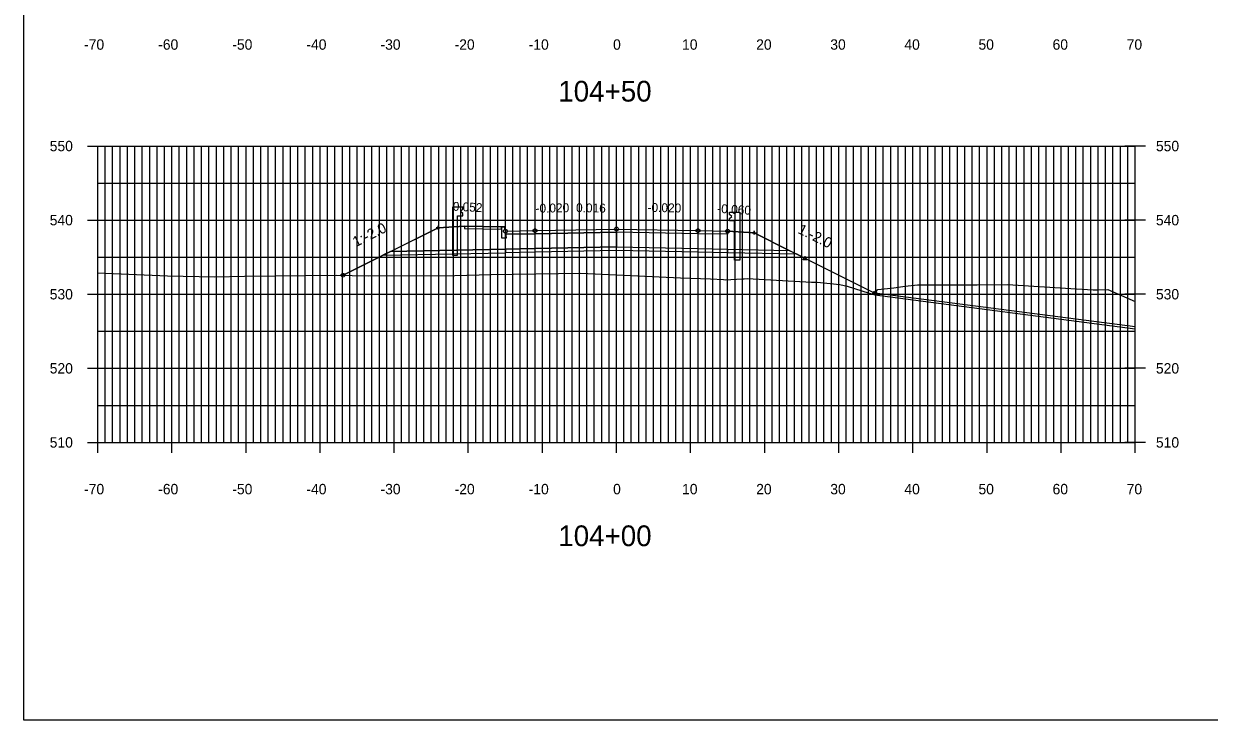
# Model space of a CAD drawing. Extents: x 1509063 to 1512863, y 401160 to 402918.
# Drawn here: x 1511822.7 to 1511982.7, y 402252.1 to 402346.1 of the extents above; entities that cross this region are included whole.
import ezdxf

# ---------------------------------------------------------------- set-up
doc = ezdxf.new("R2010")
doc.units = 0
for name, color, linetype in [('DD_P', 7, 'Continuous'), ('DDG_P', 7, 'Continuous'), ('LFILL_P', 7, 'Continuous'), ('NBL1', 7, 'Continuous'), ('PET_P', 7, 'Continuous'), ('PRC', 7, 'Continuous'), ('PSP_P', 7, 'Continuous'), ('RBS_P', 7, 'Continuous'), ('RCC_P', 7, 'Continuous'), ('RGR_P', 7, 'Continuous'), ('XAX_P', 7, 'Continuous'), ('XAXTIC_P', 7, 'Continuous'), ('XAXTXT_P_T', 7, 'Continuous'), ('XGL_P', 7, 'Continuous'), ('XSL1_P', 7, 'Continuous'), ('XSL1_P_T', 7, 'Continuous'), ('XSL2_P', 7, 'Continuous'), ('XSL3_P', 7, 'Continuous'), ('XSLOG', 7, 'Continuous')]:
    doc.layers.add(name, color=color, linetype=linetype)

msp = doc.modelspace()

# ---------------------------------------------------------------- linework, layer by layer
at = {"layer": 'DD_P'}
msp.add_lwpolyline([(1511928.15, 402314.7), (1511928.4, 402314.2), (1511927.9, 402314.2)], close=True, dxfattribs=at)
at = {"layer": 'DDG_P'}
msp.add_lwpolyline([(1511972.73, 402304.91), (1511972.73, 402305.16), (1511937.59, 402309.73), (1511937.59, 402309.48)], close=True, dxfattribs=at)
at = {"layer": 'LFILL_P'}
for points in [[(1511882.23, 402318.77), (1511878.65, 402318.56), (1511865.82, 402312.15)], [(1511917.73, 402318.08), (1511921.31, 402317.87), (1511928.15, 402314.45), (1511937.59, 402309.73)]]:
    msp.add_lwpolyline(points, dxfattribs=at)
for centre in [(1511865.82, 402312.15), (1511937.59, 402309.73)]:
    msp.add_circle(centre, 0.25, dxfattribs=at)
at = {"layer": 'NBL1'}
msp.add_lwpolyline([(1512142.73, 402252.08), (1511822.73, 402252.08), (1511822.73, 402462.08), (1512142.73, 402462.08)], close=True, dxfattribs=at)
at = {"layer": 'PET_P'}
for centre in [(1511891.73, 402318.16), (1511913.73, 402318.16)]:
    msp.add_circle(centre, 0.25, dxfattribs=at)
at = {"layer": 'PRC'}
msp.add_circle((1511902.73, 402318.38), 0.25, dxfattribs=at)
at = {"layer": 'PSP_P'}
for centre in [(1511887.73, 402318.08), (1511917.73, 402318.08)]:
    msp.add_circle(centre, 0.25, dxfattribs=at)
at = {"layer": 'RBS_P'}
for points in [[(1511887.8, 402317.67), (1511891.73, 402317.75), (1511902.73, 402317.97), (1511902.73, 402315.97), (1511891.73, 402315.75), (1511887.8, 402315.67), (1511872.24, 402315.36), (1511878.65, 402318.56), (1511882.23, 402318.77), (1511882.23, 402318.44), (1511887.23, 402318.34), (1511887.23, 402317.17), (1511887.88, 402317.17)], [(1511902.73, 402317.97), (1511902.73, 402315.97), (1511913.73, 402315.75), (1511917.73, 402315.67), (1511926.05, 402315.5), (1511921.31, 402317.87), (1511917.73, 402318.08), (1511917.73, 402317.67), (1511913.73, 402317.75)]]:
    msp.add_lwpolyline(points, close=True, dxfattribs=at)
for points in [[(1511878.65, 402318.56), (1511878.65, 402318.81), (1511878.65, 402318.56), (1511878.4, 402318.56), (1511878.65, 402318.56), (1511878.65, 402318.31), (1511878.65, 402318.56), (1511878.9, 402318.56)], [(1511921.31, 402317.87), (1511921.31, 402318.12), (1511921.31, 402317.87), (1511921.06, 402317.87), (1511921.31, 402317.87), (1511921.31, 402317.62), (1511921.31, 402317.87), (1511921.56, 402317.87)]]:
    msp.add_lwpolyline(points, dxfattribs=at)
at = {"layer": 'RCC_P'}
msp.add_lwpolyline([(1511887.73, 402318.08), (1511887.63, 402318.67), (1511887.23, 402318.67), (1511887.23, 402317.17), (1511887.88, 402317.17)], close=True, dxfattribs=at)
at = {"layer": 'RGR_P'}
for points in [[(1511881.29, 402320.18), (1511881.98, 402320.18), (1511881.98, 402320.48), (1511881.68, 402320.76), (1511881.98, 402321.05), (1511881.98, 402321.35), (1511880.6, 402321.35), (1511880.6, 402314.85), (1511881.29, 402314.85)], [(1511918.66, 402319.48), (1511917.98, 402319.48), (1511917.98, 402319.78), (1511918.28, 402320.07), (1511917.98, 402320.36), (1511917.98, 402320.66), (1511919.36, 402320.66), (1511919.36, 402314.16), (1511918.66, 402314.16)]]:
    msp.add_lwpolyline(points, close=True, dxfattribs=at)
at = {"layer": 'XAX_P'}
for p, q in [((1511832.73, 402289.58), (1511832.73, 402329.58)), ((1511902.73, 402289.58), (1511902.73, 402329.58)), ((1511972.73, 402289.58), (1511972.73, 402329.58)), ((1511832.73, 402289.58), (1511972.73, 402289.58))]:
    msp.add_line(p, q, dxfattribs=at)
at = {"layer": 'XAXTIC_P'}
for p, q in [((1511831.33, 402329.58), (1511834.13, 402329.58)), ((1511901.33, 402329.58), (1511904.13, 402329.58)), ((1511974.13, 402329.58), (1511971.33, 402329.58)), ((1511831.33, 402319.58), (1511834.13, 402319.58)), ((1511901.33, 402319.58), (1511904.13, 402319.58)), ((1511974.13, 402319.58), (1511971.33, 402319.58)), ((1511831.33, 402309.58), (1511834.13, 402309.58)), ((1511901.33, 402309.58), (1511904.13, 402309.58)), ((1511974.13, 402309.58), (1511971.33, 402309.58)), ((1511831.33, 402299.58), (1511834.13, 402299.58)), ((1511901.33, 402299.58), (1511904.13, 402299.58)), ((1511974.13, 402299.58), (1511971.33, 402299.58)), ((1511832.73, 402288.18), (1511832.73, 402290.98)), ((1511842.73, 402288.18), (1511842.73, 402290.98)), ((1511852.73, 402288.18), (1511852.73, 402290.98)), ((1511862.73, 402288.18), (1511862.73, 402290.98)), ((1511872.73, 402288.18), (1511872.73, 402290.98)), ((1511882.73, 402288.18), (1511882.73, 402290.98)), ((1511892.73, 402288.18), (1511892.73, 402290.98)), ((1511902.73, 402288.18), (1511902.73, 402290.98)), ((1511912.73, 402288.18), (1511912.73, 402290.98)), ((1511922.73, 402288.18), (1511922.73, 402290.98)), ((1511932.73, 402288.18), (1511932.73, 402290.98)), ((1511942.73, 402288.18), (1511942.73, 402290.98)), ((1511952.73, 402288.18), (1511952.73, 402290.98)), ((1511962.73, 402288.18), (1511962.73, 402290.98)), ((1511972.73, 402288.18), (1511972.73, 402290.98)), ((1511831.33, 402289.58), (1511834.13, 402289.58)), ((1511901.33, 402289.58), (1511904.13, 402289.58)), ((1511974.13, 402289.58), (1511971.33, 402289.58))]:
    msp.add_line(p, q, dxfattribs=at)
at = {"layer": 'XGL_P'}
for p, q in [((1511832.73, 402329.58), (1511972.73, 402329.58)), ((1511832.73, 402289.58), (1511832.73, 402329.58)), ((1511833.73, 402289.58), (1511833.73, 402329.58)), ((1511834.73, 402289.58), (1511834.73, 402329.58)), ((1511835.73, 402289.58), (1511835.73, 402329.58)), ((1511836.73, 402289.58), (1511836.73, 402329.58)), ((1511837.73, 402289.58), (1511837.73, 402329.58)), ((1511838.73, 402289.58), (1511838.73, 402329.58)), ((1511839.73, 402289.58), (1511839.73, 402329.58)), ((1511840.73, 402289.58), (1511840.73, 402329.58)), ((1511841.73, 402289.58), (1511841.73, 402329.58)), ((1511842.73, 402289.58), (1511842.73, 402329.58)), ((1511843.73, 402289.58), (1511843.73, 402329.58)), ((1511844.73, 402289.58), (1511844.73, 402329.58)), ((1511845.73, 402289.58), (1511845.73, 402329.58)), ((1511846.73, 402289.58), (1511846.73, 402329.58)), ((1511847.73, 402289.58), (1511847.73, 402329.58)), ((1511848.73, 402289.58), (1511848.73, 402329.58)), ((1511849.73, 402289.58), (1511849.73, 402329.58)), ((1511850.73, 402289.58), (1511850.73, 402329.58)), ((1511851.73, 402289.58), (1511851.73, 402329.58)), ((1511852.73, 402289.58), (1511852.73, 402329.58)), ((1511853.73, 402289.58), (1511853.73, 402329.58)), ((1511854.73, 402289.58), (1511854.73, 402329.58)), ((1511855.73, 402289.58), (1511855.73, 402329.58)), ((1511856.73, 402289.58), (1511856.73, 402329.58)), ((1511857.73, 402289.58), (1511857.73, 402329.58)), ((1511858.73, 402289.58), (1511858.73, 402329.58)), ((1511859.73, 402289.58), (1511859.73, 402329.58)), ((1511860.73, 402289.58), (1511860.73, 402329.58)), ((1511861.73, 402289.58), (1511861.73, 402329.58)), ((1511862.73, 402289.58), (1511862.73, 402329.58)), ((1511863.73, 402289.58), (1511863.73, 402329.58)), ((1511864.73, 402289.58), (1511864.73, 402329.58)), ((1511865.73, 402289.58), (1511865.73, 402329.58)), ((1511866.73, 402289.58), (1511866.73, 402329.58)), ((1511867.73, 402289.58), (1511867.73, 402329.58)), ((1511868.73, 402289.58), (1511868.73, 402329.58)), ((1511869.73, 402289.58), (1511869.73, 402329.58)), ((1511870.73, 402289.58), (1511870.73, 402329.58)), ((1511871.73, 402289.58), (1511871.73, 402329.58)), ((1511872.73, 402289.58), (1511872.73, 402329.58)), ((1511873.73, 402289.58), (1511873.73, 402329.58)), ((1511874.73, 402289.58), (1511874.73, 402329.58)), ((1511875.73, 402289.58), (1511875.73, 402329.58)), ((1511876.73, 402289.58), (1511876.73, 402329.58)), ((1511877.73, 402289.58), (1511877.73, 402329.58)), ((1511878.73, 402289.58), (1511878.73, 402329.58)), ((1511879.73, 402289.58), (1511879.73, 402329.58)), ((1511880.73, 402289.58), (1511880.73, 402329.58)), ((1511881.73, 402289.58), (1511881.73, 402329.58)), ((1511882.73, 402289.58), (1511882.73, 402329.58)), ((1511883.73, 402289.58), (1511883.73, 402329.58)), ((1511884.73, 402289.58), (1511884.73, 402329.58)), ((1511885.73, 402289.58), (1511885.73, 402329.58)), ((1511886.73, 402289.58), (1511886.73, 402329.58)), ((1511887.73, 402289.58), (1511887.73, 402329.58)), ((1511888.73, 402289.58), (1511888.73, 402329.58)), ((1511889.73, 402289.58), (1511889.73, 402329.58)), ((1511890.73, 402289.58), (1511890.73, 402329.58)), ((1511891.73, 402289.58), (1511891.73, 402329.58)), ((1511892.73, 402289.58), (1511892.73, 402329.58)), ((1511893.73, 402289.58), (1511893.73, 402329.58)), ((1511894.73, 402289.58), (1511894.73, 402329.58)), ((1511895.73, 402289.58), (1511895.73, 402329.58)), ((1511896.73, 402289.58), (1511896.73, 402329.58)), ((1511897.73, 402289.58), (1511897.73, 402329.58)), ((1511898.73, 402289.58), (1511898.73, 402329.58)), ((1511899.73, 402289.58), (1511899.73, 402329.58)), ((1511900.73, 402289.58), (1511900.73, 402329.58)), ((1511901.73, 402289.58), (1511901.73, 402329.58)), ((1511902.73, 402289.58), (1511902.73, 402329.58)), ((1511903.73, 402289.58), (1511903.73, 402329.58)), ((1511904.73, 402289.58), (1511904.73, 402329.58)), ((1511905.73, 402289.58), (1511905.73, 402329.58)), ((1511906.73, 402289.58), (1511906.73, 402329.58)), ((1511907.73, 402289.58), (1511907.73, 402329.58)), ((1511908.73, 402289.58), (1511908.73, 402329.58)), ((1511909.73, 402289.58), (1511909.73, 402329.58)), ((1511910.73, 402289.58), (1511910.73, 402329.58)), ((1511911.73, 402289.58), (1511911.73, 402329.58)), ((1511912.73, 402289.58), (1511912.73, 402329.58)), ((1511913.73, 402289.58), (1511913.73, 402329.58)), ((1511914.73, 402289.58), (1511914.73, 402329.58)), ((1511915.73, 402289.58), (1511915.73, 402329.58)), ((1511916.73, 402289.58), (1511916.73, 402329.58)), ((1511917.73, 402289.58), (1511917.73, 402329.58)), ((1511918.73, 402289.58), (1511918.73, 402329.58)), ((1511919.73, 402289.58), (1511919.73, 402329.58)), ((1511920.73, 402289.58), (1511920.73, 402329.58)), ((1511921.73, 402289.58), (1511921.73, 402329.58)), ((1511922.73, 402289.58), (1511922.73, 402329.58)), ((1511923.73, 402289.58), (1511923.73, 402329.58)), ((1511924.73, 402289.58), (1511924.73, 402329.58)), ((1511925.73, 402289.58), (1511925.73, 402329.58)), ((1511926.73, 402289.58), (1511926.73, 402329.58)), ((1511927.73, 402289.58), (1511927.73, 402329.58)), ((1511928.73, 402289.58), (1511928.73, 402329.58)), ((1511929.73, 402289.58), (1511929.73, 402329.58)), ((1511930.73, 402289.58), (1511930.73, 402329.58)), ((1511931.73, 402289.58), (1511931.73, 402329.58)), ((1511932.73, 402289.58), (1511932.73, 402329.58)), ((1511933.73, 402289.58), (1511933.73, 402329.58)), ((1511934.73, 402289.58), (1511934.73, 402329.58)), ((1511935.73, 402289.58), (1511935.73, 402329.58)), ((1511936.73, 402289.58), (1511936.73, 402329.58)), ((1511937.73, 402289.58), (1511937.73, 402329.58)), ((1511938.73, 402289.58), (1511938.73, 402329.58)), ((1511939.73, 402289.58), (1511939.73, 402329.58)), ((1511940.73, 402289.58), (1511940.73, 402329.58)), ((1511941.73, 402289.58), (1511941.73, 402329.58)), ((1511942.73, 402289.58), (1511942.73, 402329.58)), ((1511943.73, 402289.58), (1511943.73, 402329.58)), ((1511944.73, 402289.58), (1511944.73, 402329.58)), ((1511945.73, 402289.58), (1511945.73, 402329.58)), ((1511946.73, 402289.58), (1511946.73, 402329.58)), ((1511947.73, 402289.58), (1511947.73, 402329.58)), ((1511948.73, 402289.58), (1511948.73, 402329.58)), ((1511949.73, 402289.58), (1511949.73, 402329.58)), ((1511950.73, 402289.58), (1511950.73, 402329.58)), ((1511951.73, 402289.58), (1511951.73, 402329.58)), ((1511952.73, 402289.58), (1511952.73, 402329.58)), ((1511953.73, 402289.58), (1511953.73, 402329.58)), ((1511954.73, 402289.58), (1511954.73, 402329.58)), ((1511955.73, 402289.58), (1511955.73, 402329.58)), ((1511956.73, 402289.58), (1511956.73, 402329.58)), ((1511957.73, 402289.58), (1511957.73, 402329.58)), ((1511958.73, 402289.58), (1511958.73, 402329.58)), ((1511959.73, 402289.58), (1511959.73, 402329.58)), ((1511960.73, 402289.58), (1511960.73, 402329.58)), ((1511961.73, 402289.58), (1511961.73, 402329.58)), ((1511962.73, 402289.58), (1511962.73, 402329.58)), ((1511963.73, 402289.58), (1511963.73, 402329.58)), ((1511964.73, 402289.58), (1511964.73, 402329.58)), ((1511965.73, 402289.58), (1511965.73, 402329.58)), ((1511966.73, 402289.58), (1511966.73, 402329.58)), ((1511967.73, 402289.58), (1511967.73, 402329.58)), ((1511968.73, 402289.58), (1511968.73, 402329.58)), ((1511969.73, 402289.58), (1511969.73, 402329.58)), ((1511970.73, 402289.58), (1511970.73, 402329.58)), ((1511971.73, 402289.58), (1511971.73, 402329.58)), ((1511972.73, 402289.58), (1511972.73, 402329.58)), ((1511832.73, 402324.58), (1511972.73, 402324.58)), ((1511832.73, 402319.58), (1511972.73, 402319.58)), ((1511832.73, 402314.58), (1511972.73, 402314.58)), ((1511832.73, 402309.58), (1511972.73, 402309.58)), ((1511832.73, 402304.58), (1511972.73, 402304.58)), ((1511832.73, 402299.58), (1511972.73, 402299.58)), ((1511832.73, 402294.58), (1511972.73, 402294.58)), ((1511832.73, 402289.58), (1511972.73, 402289.58))]:
    msp.add_line(p, q, dxfattribs=at)
at = {"layer": 'XSL1_P'}
msp.add_lwpolyline([(1511865.82, 402312.15), (1511872.24, 402315.36), (1511878.65, 402318.56), (1511882.23, 402318.77), (1511887.23, 402318.67), (1511887.63, 402318.67), (1511887.73, 402318.08), (1511891.73, 402318.16), (1511902.73, 402318.38), (1511913.73, 402318.16), (1511917.73, 402318.08), (1511921.31, 402317.87), (1511926.05, 402315.5), (1511927.09, 402314.98), (1511928.15, 402314.45), (1511937.59, 402309.73)], dxfattribs=at)
msp.add_lwpolyline([(1511887.23, 402318.67), (1511882.23, 402318.77), (1511882.23, 402318.44), (1511887.23, 402318.34)], close=True, dxfattribs=at)
at = {"layer": 'XSL2_P'}
for points in [[(1511887.8, 402315.67), (1511872.24, 402315.36), (1511871.2, 402314.84), (1511887.8, 402315.17)], [(1511913.73, 402315.25), (1511902.73, 402315.47), (1511891.73, 402315.25), (1511887.8, 402315.17), (1511887.8, 402315.67), (1511891.73, 402315.75), (1511902.73, 402315.97), (1511913.73, 402315.75), (1511917.73, 402315.67), (1511917.73, 402315.17)], [(1511917.73, 402315.67), (1511926.05, 402315.5), (1511927.09, 402314.98), (1511917.73, 402315.17)]]:
    msp.add_lwpolyline(points, close=True, dxfattribs=at)
for points in [[(1511872.24, 402315.36), (1511887.8, 402315.67)], [(1511917.73, 402315.67), (1511926.05, 402315.5)]]:
    msp.add_lwpolyline(points, dxfattribs=at)
at = {"layer": 'XSL3_P'}
msp.add_lwpolyline([(1511891.73, 402317.75), (1511887.8, 402317.67), (1511887.73, 402318.08), (1511891.73, 402318.16), (1511902.73, 402318.38), (1511913.73, 402318.16), (1511917.73, 402318.08), (1511917.73, 402317.67), (1511913.73, 402317.75), (1511902.73, 402317.97)], close=True, dxfattribs=at)
at = {"layer": 'XSLOG'}
msp.add_lwpolyline([(1511832.73, 402312.49), (1511842.15, 402312.08), (1511848.53, 402311.92), (1511852.51, 402312.02), (1511864.88, 402312.17), (1511869.2, 402312.07), (1511880.89, 402312.1), (1511885.82, 402312.25), (1511897.93, 402312.41), (1511911.36, 402311.78), (1511915.41, 402311.66), (1511917.19, 402311.57), (1511917.42, 402311.52), (1511919.66, 402311.68), (1511919.95, 402311.66), (1511920.39, 402311.69), (1511929.03, 402311.23), (1511929.79, 402311.2), (1511932.86, 402310.89), (1511933.86, 402310.68), (1511936.83, 402309.73), (1511937.45, 402309.57), (1511938.01, 402310.21), (1511940.15, 402310.45), (1511941.68, 402310.65), (1511943.37, 402310.86), (1511951.42, 402310.87), (1511955.48, 402310.88), (1511964.04, 402310.37), (1511967.05, 402310.19), (1511967.24, 402310.19), (1511967.69, 402310.18), (1511969.02, 402310.22), (1511972.73, 402308.6)], dxfattribs=at)

# ---------------------------------------------------------------- texts
at = {"layer": 'XAXTXT_P_T'}
for s, height, p in [('-70', 1.4, (1511830.88, 402342.58)), ('-60', 1.4, (1511840.88, 402342.58)), ('-50', 1.4, (1511850.88, 402342.58)), ('-40', 1.4, (1511860.88, 402342.58)), ('-30', 1.4, (1511870.88, 402342.58)), ('-20', 1.4, (1511880.88, 402342.58)), ('-10', 1.4, (1511890.88, 402342.58)), ('0', 1.4, (1511902.27, 402342.58)), ('10', 1.4, (1511911.58, 402342.58)), ('20', 1.4, (1511921.58, 402342.58)), ('30', 1.4, (1511931.58, 402342.58)), ('40', 1.4, (1511941.58, 402342.58)), ('50', 1.4, (1511951.58, 402342.58)), ('60', 1.4, (1511961.58, 402342.58)), ('70', 1.4, (1511971.58, 402342.58)), ('104+50', 2.8, (1511894.87, 402335.58)), ('550', 1.4, (1511826.24, 402328.88)), ('550', 1.4, (1511975.53, 402328.88)), ('540', 1.4, (1511826.24, 402318.88)), ('540', 1.4, (1511975.53, 402318.88)), ('530', 1.4, (1511826.24, 402308.88)), ('530', 1.4, (1511975.53, 402308.88)), ('520', 1.4, (1511826.24, 402298.88)), ('520', 1.4, (1511975.53, 402298.88)), ('510', 1.4, (1511826.24, 402288.88)), ('510', 1.4, (1511975.53, 402288.88)), ('-70', 1.4, (1511830.88, 402282.58)), ('-60', 1.4, (1511840.88, 402282.58)), ('-50', 1.4, (1511850.88, 402282.58)), ('-40', 1.4, (1511860.88, 402282.58)), ('-30', 1.4, (1511870.88, 402282.58)), ('-20', 1.4, (1511880.88, 402282.58)), ('-10', 1.4, (1511890.88, 402282.58)), ('0', 1.4, (1511902.27, 402282.58)), ('10', 1.4, (1511911.58, 402282.58)), ('20', 1.4, (1511921.58, 402282.58)), ('30', 1.4, (1511931.58, 402282.58)), ('40', 1.4, (1511941.58, 402282.58)), ('50', 1.4, (1511951.58, 402282.58)), ('60', 1.4, (1511961.58, 402282.58)), ('70', 1.4, (1511971.58, 402282.58)), ('104+00', 2.8, (1511894.87, 402275.58))]:
    msp.add_text(s, height=height, dxfattribs=at).set_placement(p)
at = {"layer": 'XSL1_P_T'}
for s, height, rotation, p in [('0.052', 1.2, 356.9978, (1511880.6, 402320.86)), ('-0.020', 1.2, 1.1458, (1511891.81, 402320.57)), ('0.016', 1.2, 359.0716, (1511897.26, 402320.66)), ('0.016', 1.2, 359.0716, (1511897.26, 402320.66)), ('-0.020', 1.2, 358.8542, (1511906.91, 402320.7)), ('-0.060', 1.2, 356.5664, (1511916.3, 402320.57)), ('1:-2.0', 1.4, 26.5651, (1511867.55, 402315.92)), ('1:-2.0', 1.4, 26.5651, (1511867.55, 402315.92)), ('1:-2.0', 1.4, 26.5651, (1511867.55, 402315.92)), ('1:-2.0', 1.4, 333.4349, (1511927.1, 402317.88)), ('1:-2.0', 1.4, 333.4349, (1511927.1, 402317.88)), ('1:-2.0', 1.4, 333.4349, (1511927.1, 402317.88))]:
    msp.add_text(s, height=height, rotation=rotation, dxfattribs=at).set_placement(p)

doc.saveas('drawing.dxf')
